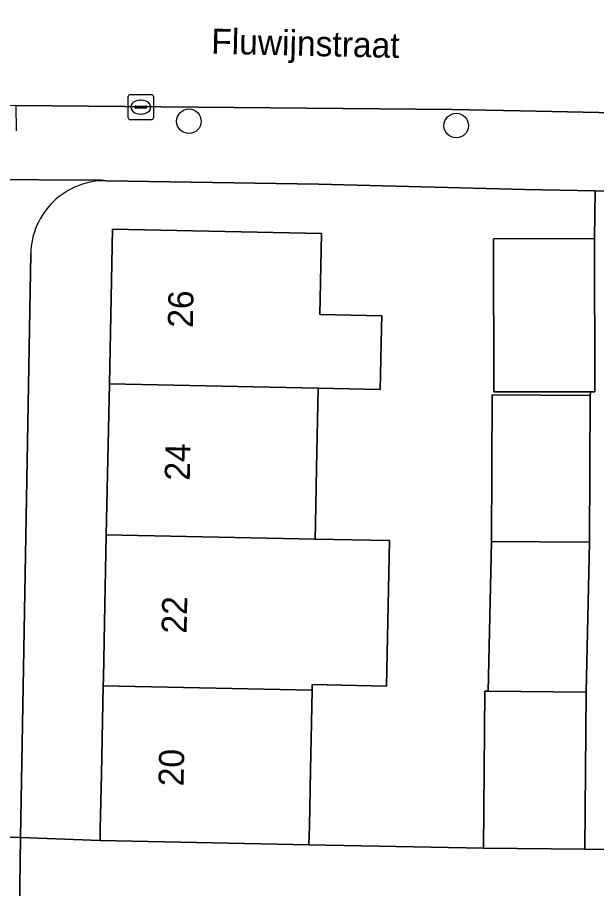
# Model space of a CAD drawing. Extents: x 160023 to 161302, y 384750 to 385707.
# Drawn here: x 160625.39 to 160648.47, y 385103.94 to 385138.66 of the extents above; entities that cross this region are included whole.
import ezdxf

# ---------------------------------------------------------------- set-up
doc = ezdxf.new("R2010")
doc.units = 0
for name, color, linetype in [('IMGEO_Boom', 7, 'Continuous'), ('IMGEO_Erf', 7, 'Continuous'), ('IMGEO_Kolk', 7, 'Continuous'), ('IMGEO_Muur', 7, 'Continuous'), ('IMGEO_Openbare_ruimte_label', 7, 'Continuous'), ('IMGEO_Pand', 7, 'Continuous'), ('IMGEO_Pand_nummerreeks', 7, 'Continuous'), ('IMGEO_Rijbaan_lokaal_open', 7, 'Continuous'), ('IMGEO_Voetpad_open', 7, 'Continuous')]:
    doc.layers.add(name, color=color, linetype=linetype)

msp = doc.modelspace()

# ---------------------------------------------------------------- linework, layer by layer
at = {"layer": 'IMGEO_Boom'}
for centre in [(160632.223, 385134.525), (160642.876, 385134.354)]:
    msp.add_circle(centre, 0.489, dxfattribs=at)
at = {"layer": 'IMGEO_Erf'}
for points in [[(160644.363, 385129.841), (160648.38, 385129.851), (160648.418, 385131.752), (160645.612, 385131.808), (160637.393, 385132.013), (160628.945, 385132.154)], [(160625.922, 385129.247), (160625.507, 385105.974), (160628.685, 385105.853), (160628.694, 385106.304), (160628.739, 385108.504), (160628.81, 385112.021), (160628.816, 385112.333), (160628.861, 385114.534), (160628.932, 385118.039), (160629.053, 385124.057), (160629.178, 385130.224), (160637.501, 385130.055), (160637.435, 385126.822), (160639.911, 385126.772), (160639.901, 385126.273), (160639.851, 385123.838), (160637.376, 385123.888), (160637.312, 385120.683), (160637.267, 385118.482), (160637.255, 385117.87), (160640.211, 385117.81), (160640.093, 385112.016), (160637.138, 385112.076), (160637.133, 385111.852), (160637.068, 385108.634), (160637.023, 385106.433), (160637.008, 385105.684), (160643.958, 385105.551), (160644.014, 385111.808), (160644.151, 385111.807), (160644.277, 385117.776), (160644.315, 385123.622), (160648.22, 385123.595), (160648.221, 385123.744), (160644.377, 385123.735), (160644.363, 385129.841)]]:
    msp.add_lwpolyline(points, dxfattribs=at)
msp.add_arc((160628.882, 385129.194), 2.961, 88.7852, 178.9735, dxfattribs=at)
at = {"layer": 'IMGEO_Kolk'}
for p, q in [((160629.881, 385135.587), (160630.733, 385135.587)), ((160629.806, 385134.661), (160629.806, 385135.513)), ((160630.294, 385135.367), (160630.319, 385135.367)), ((160630.807, 385135.513), (160630.807, 385134.661)), ((160630.065, 385135.081), (160630.065, 385135.093)), ((160630.503, 385135.044), (160630.105, 385135.044)), ((160630.108, 385135.13), (160630.506, 385135.13)), ((160630.549, 385135.093), (160630.549, 385135.081)), ((160630.733, 385134.587), (160629.881, 385134.587)), ((160630.317, 385134.807), (160630.292, 385134.807))]:
    msp.add_line(p, q, dxfattribs=at)
for points in [[(160629.881, 385135.587), (160630.733, 385135.587)], [(160629.806, 385134.661), (160629.806, 385135.513)], [(160630.807, 385135.513), (160630.807, 385134.661)], [(160630.733, 385134.587), (160629.881, 385134.587)]]:
    msp.add_lwpolyline(points, dxfattribs=at)
for centre, radius, start, end in [((160629.883, 385135.511), 0.0765, 91.552, 178.448), ((160629.883, 385135.511), 0.0765, 91.552, 178.448), ((160630.731, 385135.511), 0.0765, 1.552, 88.448), ((160630.731, 385135.511), 0.0765, 1.552, 88.448), ((160630.105, 385135.09), 0.0403, 85.8775, 175.7526), ((160630.102, 385135.08), 0.0366, 178.938, 274.7102), ((160630.506, 385135.087), 0.043, 264.8664, 352.4533), ((160630.51, 385135.092), 0.0386, 1.7309, 96.639), ((160629.883, 385134.663), 0.0765, 181.552, 268.448), ((160629.883, 385134.663), 0.0765, 181.552, 268.448), ((160630.731, 385134.663), 0.0765, 271.552, 358.448), ((160630.731, 385134.663), 0.0765, 271.552, 358.448)]:
    msp.add_arc(centre, radius, start, end, dxfattribs=at)
for centre, major_axis, ratio, start_param, end_param in [((160630.293, 385135.087), (-0.387, 0.002), 0.722429, 4.712389, 7.853982), ((160630.318, 385135.087), (-0.39, 0.002), 0.717154, 1.570796, 4.712389)]:
    msp.add_ellipse(centre, major_axis=major_axis, ratio=ratio, start_param=start_param, end_param=end_param, dxfattribs=at)
at = {"layer": 'IMGEO_Muur'}
for points in [[(160637.393, 385132.013), (160645.612, 385131.808)], [(160637.008, 385105.684), (160643.958, 385105.551)]]:
    msp.add_lwpolyline(points, dxfattribs=at)
at = {"layer": 'IMGEO_Pand'}
for points in [[(160637.501, 385130.055), (160629.178, 385130.224), (160629.053, 385124.057), (160637.376, 385123.888), (160639.851, 385123.838), (160639.901, 385126.273), (160639.911, 385126.772), (160637.435, 385126.822)], [(160648.38, 385129.851), (160644.363, 385129.841), (160644.377, 385123.735), (160648.221, 385123.744), (160648.394, 385123.744)], [(160637.312, 385120.683), (160637.376, 385123.888), (160629.053, 385124.057), (160628.932, 385118.039), (160637.255, 385117.87), (160637.267, 385118.482)], [(160648.22, 385123.595), (160644.315, 385123.622), (160644.277, 385117.776), (160648.183, 385117.75)], [(160640.211, 385117.81), (160637.255, 385117.87), (160628.932, 385118.039), (160628.861, 385114.534), (160628.816, 385112.333), (160628.81, 385112.021), (160637.133, 385111.852), (160637.138, 385112.076), (160640.093, 385112.016)], [(160648.183, 385117.75), (160644.277, 385117.776), (160644.151, 385111.807), (160648.057, 385111.771)], [(160637.068, 385108.634), (160637.133, 385111.852), (160628.81, 385112.021), (160628.739, 385108.504), (160628.694, 385106.304), (160628.685, 385105.853), (160637.008, 385105.684), (160637.023, 385106.433)], [(160648.057, 385111.771), (160644.151, 385111.807), (160644.014, 385111.808), (160643.958, 385105.551), (160648.001, 385105.514)]]:
    msp.add_lwpolyline(points, close=True, dxfattribs=at)
at = {"layer": 'IMGEO_Rijbaan_lokaal_open'}
msp.add_lwpolyline([(160618.285, 385142.851), (160600.937, 385147.931), (160598.653, 385140.29), (160610.834, 385136.684), (160615.494, 385135.722), (160620.457, 385135.198), (160625.332, 385135.154), (160642.715, 385134.997), (160645.444, 385134.941), (160648.556, 385134.877), (160649.701, 385134.854), (160653.281, 385134.781), (160669.265, 385134.453), (160669.714, 385134.443), (160669.833, 385140.397), (160627.726, 385141.4), (160623.449, 385141.825)], dxfattribs=at)
msp.add_lwpolyline([(160672.024, 385105.162), (160669.136, 385105.156), (160661.759, 385105.29), (160657.76, 385105.344), (160652.724, 385105.411), (160649.545, 385105.482), (160648.001, 385105.514), (160643.958, 385105.551), (160637.008, 385105.684), (160628.685, 385105.853), (160625.507, 385105.974), (160625.449, 385101.157), (160625.445, 385100.857), (160628.515, 385100.842), (160636.89, 385100.688), (160643.969, 385100.561), (160647.203, 385100.453), (160648.14, 385100.422), (160649.595, 385100.412), (160657.747, 385100.327), (160661.746, 385100.285), (160669.124, 385100.133), (160671.933, 385100.035)], close=True, dxfattribs=at)
at = {"layer": 'IMGEO_Voetpad_open'}
for points in [[(160676.398, 385134.302), (160669.714, 385134.443), (160669.265, 385134.453), (160653.281, 385134.781), (160649.701, 385134.854), (160648.556, 385134.877), (160645.444, 385134.941), (160642.715, 385134.997), (160625.332, 385135.154), (160625.336, 385134.137)], [(160617.723, 385128.133), (160617.844, 385132.455), (160623.722, 385132.207), (160628.745, 385132.176), (160628.945, 385132.154), (160637.393, 385132.013), (160645.612, 385131.808), (160648.418, 385131.752), (160650.068, 385131.719), (160653.249, 385131.655), (160663.216, 385131.451), (160669.819, 385131.285)], [(160628.945, 385132.154), (160628.745, 385132.176), (160623.722, 385132.207), (160623.082, 385106.004), (160625.507, 385105.974), (160625.922, 385129.247)]]:
    msp.add_lwpolyline(points, dxfattribs=at)
for points in [[(160649.872, 385117.456), (160649.959, 385120.613), (160649.864, 385123.756), (160650.03, 385129.797), (160650.068, 385131.719), (160648.418, 385131.752), (160648.38, 385129.851), (160648.394, 385123.744), (160648.221, 385123.744), (160648.22, 385123.595), (160648.183, 385117.75), (160648.057, 385111.771), (160648.001, 385105.514), (160649.545, 385105.482), (160649.617, 385108.739), (160649.793, 385114.572)], [(160625.449, 385101.157), (160625.507, 385105.974), (160623.082, 385106.004), (160622.965, 385101.188)]]:
    msp.add_lwpolyline(points, close=True, dxfattribs=at)
msp.add_arc((160628.882, 385129.194), 2.961, 88.7852, 178.9735, dxfattribs=at)

# ---------------------------------------------------------------- texts
at = {"layer": 'IMGEO_Openbare_ruimte_label'}
msp.add_text('Fluwijnstraat', height=1, rotation=358.6824, dxfattribs=at).set_placement((160633.104, 385137.219))
at = {"layer": 'IMGEO_Pand_nummerreeks'}
for s, rotation, p in [('26', 88.8428, (160632.38, 385126.285)), ('24', 88.8411, (160632.257, 385120.192)), ('22', 88.8428, (160632.132, 385114.096)), ('20', 88.8411, (160632.01, 385108.01))]:
    msp.add_text(s, height=1, rotation=rotation, dxfattribs=at).set_placement(p)

doc.saveas('drawing.dxf')
